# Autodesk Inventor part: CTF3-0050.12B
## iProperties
Shininess: 64.0
Length Units: 11269
Angle Units: 11279
Time Units: 11290
Mass Units: 11283
Length Display Precision: 3
Angle Display Precision: 2
Compacted: True
Part Number: CTF3-0050.12B
Document SubType Name: Modeling
Created: 2003-12
Designer: Lollo
Density: 0.0
Volumn: 0.0
Area: 0.0
PropertySet Name: Model Information
Control State: 0
Master: False
Checked Out: False
Author: Lollo
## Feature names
1. Estrusione1 [Extrusion]
2. Estrusione2 [Extrusion]
3. Smusso2 [Chamfer]
4. Estrusione3 [Extrusion]
5. Estrusione4 [Extrusion]
6. Estrusione5 [Extrusion]
7. Estrusione6 [Extrusion]
8. Smusso3 [Chamfer]
